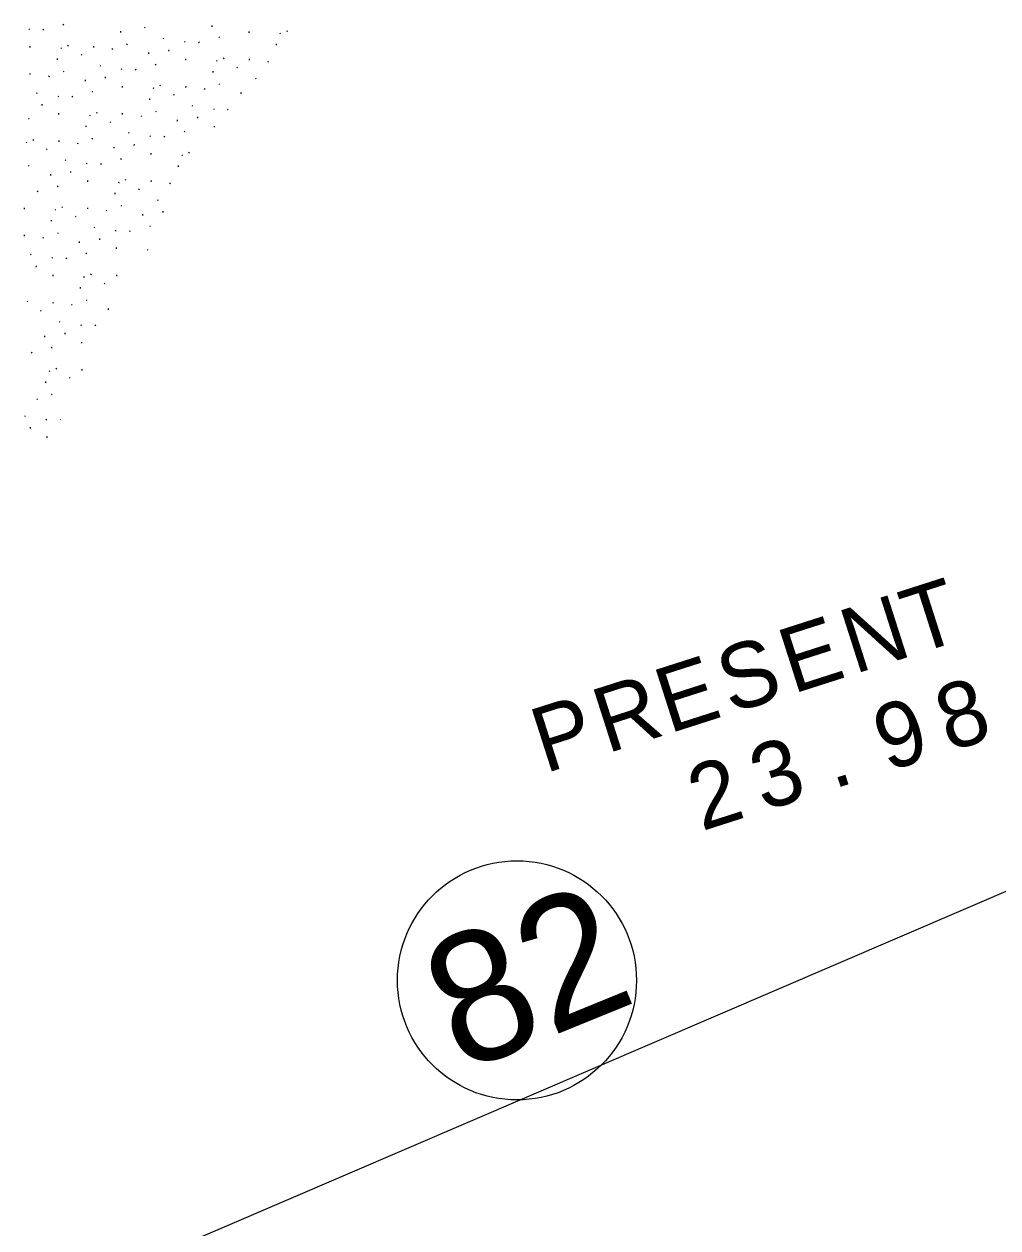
# Model space of a CAD drawing. Extents: x 1621035 to 1623496, y 1102384 to 1103996.
# Drawn here: x 1622275.9 to 1622365.9, y 1102744 to 1102855.1 of the extents above; entities that cross this region are included whole.
import ezdxf

# ---------------------------------------------------------------- set-up
doc = ezdxf.new("R2010")
doc.units = 0
for name, color, linetype in [('RD_EX_DV_TX_Prop', 7, 'Continuous'), ('RD_EX_Misc', 7, 'Continuous'), ('RD_EX_RW', 7, 'Continuous'), ('RD_PD_Final_TX', 7, 'Continuous')]:
    doc.layers.add(name, color=color, linetype=linetype)

msp = doc.modelspace()

# ---------------------------------------------------------------- linework, layer by layer
at = {"layer": 'RD_EX_Misc'}
msp.add_circle((1622321.46, 1102766.86), 11.04, dxfattribs=at)
at = {"layer": 'RD_EX_RW'}
for p, q in [((1622279.52, 1102855.12), (1622279.6, 1102855.07)), ((1622287.05, 1102854.84), (1622287.12, 1102854.8)), ((1622293.31, 1102854.9), (1622293.31, 1102855.02)), ((1622276.37, 1102854.69), (1622276.44, 1102854.65)), ((1622277.67, 1102854.67), (1622277.73, 1102854.58)), ((1622284.87, 1102854.36), (1622284.87, 1102854.48)), ((1622288.77, 1102853.83), (1622288.84, 1102853.78)), ((1622293.91, 1102853.95), (1622293.98, 1102853.9)), ((1622296.73, 1102854.32), (1622296.73, 1102854.44)), ((1622299.55, 1102854.29), (1622299.62, 1102854.24)), ((1622300.18, 1102854.53), (1622300.26, 1102854.48)), ((1622276.48, 1102852.98), (1622276.49, 1102853.09)), ((1622279.31, 1102852.94), (1622279.38, 1102852.89)), ((1622279.94, 1102853.18), (1622280.02, 1102853.14)), ((1622282.36, 1102852.99), (1622282.37, 1102853.1)), ((1622284.04, 1102852.87), (1622284.12, 1102852.82)), ((1622285.4, 1102853.31), (1622285.47, 1102853.26)), ((1622289.31, 1102852.65), (1622289.32, 1102852.77)), ((1622290.75, 1102853.52), (1622290.82, 1102853.48)), ((1622292.05, 1102853.5), (1622292.11, 1102853.41)), ((1622299.25, 1102853.19), (1622299.25, 1102853.31)), ((1622279.01, 1102851.84), (1622279.01, 1102851.96)), ((1622281.19, 1102852.33), (1622281.26, 1102852.28)), ((1622287.45, 1102852.39), (1622287.45, 1102852.51)), ((1622288.05, 1102851.44), (1622288.12, 1102851.39)), ((1622290.87, 1102851.81), (1622290.87, 1102851.93)), ((1622293.69, 1102851.77), (1622293.76, 1102851.72)), ((1622294.32, 1102852.02), (1622294.4, 1102851.97)), ((1622296.74, 1102851.82), (1622296.75, 1102851.94)), ((1622298.42, 1102851.7), (1622298.5, 1102851.66)), ((1622276.5, 1102850.47), (1622276.5, 1102850.59)), ((1622278.18, 1102850.36), (1622278.26, 1102850.31)), ((1622279.54, 1102850.8), (1622279.61, 1102850.75)), ((1622282.91, 1102851.32), (1622282.98, 1102851.27)), ((1622284.89, 1102851.01), (1622284.96, 1102850.96)), ((1622286.19, 1102850.99), (1622286.25, 1102850.89)), ((1622293.39, 1102850.68), (1622293.39, 1102850.79)), ((1622295.57, 1102851.16), (1622295.64, 1102851.11)), ((1622281.59, 1102849.87), (1622281.59, 1102849.99)), ((1622283.45, 1102850.14), (1622283.46, 1102850.26)), ((1622285.01, 1102849.29), (1622285.01, 1102849.41)), ((1622287.83, 1102849.26), (1622287.9, 1102849.21)), ((1622288.46, 1102849.5), (1622288.54, 1102849.45)), ((1622290.88, 1102849.3), (1622290.89, 1102849.42)), ((1622293.92, 1102849.63), (1622293.99, 1102849.58)), ((1622297.29, 1102850.15), (1622297.36, 1102850.1)), ((1622277.05, 1102848.8), (1622277.12, 1102848.75)), ((1622279.03, 1102848.49), (1622279.1, 1102848.45)), ((1622280.33, 1102848.47), (1622280.39, 1102848.38)), ((1622282.18, 1102848.92), (1622282.26, 1102848.87)), ((1622287.53, 1102848.16), (1622287.53, 1102848.28)), ((1622289.71, 1102848.64), (1622289.78, 1102848.6)), ((1622292.56, 1102849.19), (1622292.64, 1102849.14)), ((1622295.97, 1102848.7), (1622295.97, 1102848.82)), ((1622277.59, 1102847.62), (1622277.6, 1102847.74)), ((1622288.06, 1102847.11), (1622288.13, 1102847.07)), ((1622291.43, 1102847.63), (1622291.5, 1102847.59)), ((1622293.41, 1102847.33), (1622293.48, 1102847.28)), ((1622294.71, 1102847.3), (1622294.77, 1102847.21)), ((1622276.32, 1102846.41), (1622276.4, 1102846.36)), ((1622279.15, 1102846.78), (1622279.15, 1102846.9)), ((1622281.97, 1102846.74), (1622282.04, 1102846.69)), ((1622282.6, 1102846.99), (1622282.68, 1102846.94)), ((1622283.85, 1102846.13), (1622283.92, 1102846.08)), ((1622285.02, 1102846.79), (1622285.03, 1102846.9)), ((1622286.7, 1102846.67), (1622286.78, 1102846.63)), ((1622290.11, 1102846.19), (1622290.11, 1102846.31)), ((1622291.98, 1102846.46), (1622291.98, 1102846.57)), ((1622281.67, 1102845.65), (1622281.67, 1102845.76)), ((1622285.57, 1102845.12), (1622285.64, 1102845.07)), ((1622287.55, 1102844.81), (1622287.62, 1102844.76)), ((1622288.85, 1102844.79), (1622288.91, 1102844.69)), ((1622290.71, 1102845.24), (1622290.78, 1102845.19)), ((1622293.53, 1102845.61), (1622293.53, 1102845.73)), ((1622276.11, 1102844.23), (1622276.18, 1102844.18)), ((1622276.74, 1102844.47), (1622276.82, 1102844.42)), ((1622279.16, 1102844.27), (1622279.17, 1102844.39)), ((1622280.84, 1102844.16), (1622280.92, 1102844.11)), ((1622282.2, 1102844.6), (1622282.27, 1102844.55)), ((1622284.25, 1102843.67), (1622284.25, 1102843.79)), ((1622286.11, 1102843.94), (1622286.12, 1102844.06)), ((1622277.99, 1102843.61), (1622278.06, 1102843.57)), ((1622279.71, 1102842.6), (1622279.78, 1102842.55)), ((1622284.84, 1102842.72), (1622284.92, 1102842.68)), ((1622287.67, 1102843.09), (1622287.67, 1102843.21)), ((1622290.49, 1102843.06), (1622290.56, 1102843.01)), ((1622291.12, 1102843.3), (1622291.2, 1102843.25)), ((1622276.34, 1102842.08), (1622276.41, 1102842.03)), ((1622280.25, 1102841.43), (1622280.26, 1102841.54)), ((1622281.69, 1102842.3), (1622281.76, 1102842.25)), ((1622282.99, 1102842.27), (1622283.05, 1102842.18)), ((1622290.19, 1102841.96), (1622290.19, 1102842.08)), ((1622278.39, 1102841.16), (1622278.39, 1102841.28)), ((1622281.81, 1102840.58), (1622281.81, 1102840.7)), ((1622284.63, 1102840.54), (1622284.7, 1102840.5)), ((1622285.26, 1102840.79), (1622285.34, 1102840.74)), ((1622287.68, 1102840.59), (1622287.69, 1102840.71)), ((1622289.36, 1102840.47), (1622289.44, 1102840.43)), ((1622277.13, 1102839.76), (1622277.19, 1102839.66)), ((1622278.98, 1102840.21), (1622279.06, 1102840.16)), ((1622284.33, 1102839.45), (1622284.33, 1102839.57)), ((1622286.51, 1102839.93), (1622286.58, 1102839.88)), ((1622275.95, 1102838.06), (1622275.95, 1102838.18)), ((1622279.4, 1102838.27), (1622279.48, 1102838.22)), ((1622281.82, 1102838.07), (1622281.83, 1102838.19)), ((1622284.86, 1102838.4), (1622284.93, 1102838.35)), ((1622288.23, 1102838.92), (1622288.3, 1102838.87)), ((1622278.47, 1102836.93), (1622278.47, 1102837.05)), ((1622278.77, 1102838.03), (1622278.84, 1102837.98)), ((1622280.65, 1102837.42), (1622280.72, 1102837.37)), ((1622283.5, 1102837.96), (1622283.58, 1102837.91)), ((1622286.91, 1102837.48), (1622286.91, 1102837.59)), ((1622288.78, 1102837.74), (1622288.78, 1102837.86)), ((1622279, 1102835.88), (1622279.07, 1102835.84)), ((1622282.37, 1102836.4), (1622282.44, 1102836.36)), ((1622284.35, 1102836.1), (1622284.42, 1102836.05)), ((1622285.65, 1102836.08), (1622285.71, 1102835.98)), ((1622287.51, 1102836.52), (1622287.58, 1102836.48)), ((1622275.96, 1102835.56), (1622275.97, 1102835.68)), ((1622277.64, 1102835.44), (1622277.72, 1102835.4)), ((1622281.05, 1102834.96), (1622281.05, 1102835.08)), ((1622282.91, 1102835.23), (1622282.92, 1102835.35)), ((1622276.51, 1102833.89), (1622276.58, 1102833.84)), ((1622281.64, 1102834.01), (1622281.72, 1102833.96)), ((1622284.47, 1102834.38), (1622284.47, 1102834.5)), ((1622287.29, 1102834.34), (1622287.36, 1102834.3)), ((1622277.05, 1102832.71), (1622277.06, 1102832.83)), ((1622278.49, 1102833.58), (1622278.56, 1102833.53)), ((1622279.79, 1102833.56), (1622279.85, 1102833.47)), ((1622278.61, 1102831.86), (1622278.61, 1102831.98)), ((1622281.43, 1102831.83), (1622281.5, 1102831.78)), ((1622282.06, 1102832.07), (1622282.14, 1102832.03)), ((1622284.48, 1102831.87), (1622284.49, 1102831.99)), ((1622281.13, 1102830.73), (1622281.13, 1102830.85)), ((1622283.31, 1102831.22), (1622283.38, 1102831.17)), ((1622276.2, 1102829.56), (1622276.28, 1102829.51)), ((1622278.62, 1102829.36), (1622278.63, 1102829.48)), ((1622280.3, 1102829.25), (1622280.38, 1102829.2)), ((1622281.66, 1102829.68), (1622281.73, 1102829.64)), ((1622277.45, 1102828.7), (1622277.52, 1102828.65)), ((1622283.71, 1102828.76), (1622283.71, 1102828.88)), ((1622279.17, 1102827.69), (1622279.24, 1102827.64)), ((1622281.15, 1102827.38), (1622281.22, 1102827.34)), ((1622282.45, 1102827.36), (1622282.51, 1102827.27)), ((1622277.85, 1102826.25), (1622277.85, 1102826.37)), ((1622279.71, 1102826.51), (1622279.72, 1102826.63)), ((1622276.59, 1102824.85), (1622276.65, 1102824.75)), ((1622278.44, 1102825.3), (1622278.52, 1102825.25)), ((1622281.27, 1102825.67), (1622281.27, 1102825.78)), ((1622278.23, 1102823.12), (1622278.3, 1102823.07)), ((1622278.86, 1102823.36), (1622278.94, 1102823.31)), ((1622281.28, 1102823.16), (1622281.29, 1102823.28)), ((1622277.93, 1102822.02), (1622277.93, 1102822.14)), ((1622280.11, 1102822.5), (1622280.18, 1102822.46)), ((1622277.1, 1102820.53), (1622277.18, 1102820.48)), ((1622278.46, 1102820.97), (1622278.53, 1102820.92)), ((1622275.97, 1102818.98), (1622276.04, 1102818.93)), ((1622277.95, 1102818.67), (1622278.02, 1102818.62)), ((1622279.25, 1102818.65), (1622279.29, 1102818.59)), ((1622276.51, 1102817.8), (1622276.52, 1102817.92)), ((1622278.07, 1102816.95), (1622278.07, 1102817.07))]:
    msp.add_line(p, q, dxfattribs=at)
at = {"layer": 'RD_PD_Final_TX'}
msp.add_lwpolyline([(1621300.09, 1102746.85), (1621324.02, 1102752.88), (1621344.3, 1102622.52), (1621455.74, 1102384.16), (1622813.61, 1102966.94), (1622454.69, 1103803.24), (1622329.06, 1103749.66), (1622314.99, 1103780.87), (1621083.19, 1103252.2)], close=True, dxfattribs=at)
msp.add_lwpolyline([(1621300.09, 1102746.85), (1621324.02, 1102752.88), (1621344.3, 1102622.52), (1621455.74, 1102384.16), (1622813.61, 1102966.94), (1622454.69, 1103803.24), (1622329.06, 1103749.66), (1622314.99, 1103780.87), (1621083.19, 1103252.2)], close=True, dxfattribs=at)

# ---------------------------------------------------------------- texts
at = {"layer": 'RD_EX_DV_TX_Prop'}
for s, p in [('T', (1622358.22, 1102796.9)), ('N', (1622352.62, 1102795.11)), ('E', (1622346.93, 1102793.28)), ('S', (1622341.19, 1102791.44)), ('E', (1622335.5, 1102789.62)), ('R', (1622329.76, 1102787.78)), ('8', (1622361.37, 1102787.93)), ('P', (1622324.05, 1102785.95)), ('9', (1622355.65, 1102786.1)), ('3', (1622344.23, 1102782.44)), ('2', (1622338.51, 1102780.61)), ('.', (1622350.66, 1102784.5))]:
    msp.add_text(s, height=6, rotation=17.7698, dxfattribs=at).set_placement(p)
at = {"layer": 'RD_EX_Misc'}
msp.add_text('82', height=12, rotation=22.1585, dxfattribs=at).set_placement((1622316.3, 1102758.28))

doc.saveas('drawing.dxf')
